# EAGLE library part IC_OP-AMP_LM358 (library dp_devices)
Dual op-amp
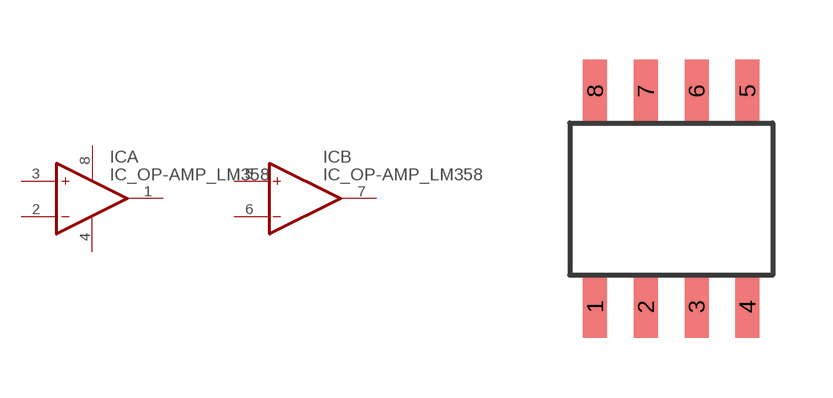
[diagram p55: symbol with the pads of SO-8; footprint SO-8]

Designator prefix IC; gates A=OPAMP_V+- B=OPAMP

## IC_OP-AMP_LM358-SO8  [SO-8]
1  A:OUT  out
2  A:-  in
3  A:+  in
4  A:V-  sup
5  B:+  in
6  B:-  in
7  B:OUT  out
8  A:V+  sup

## Footprint SO-8 (pad centres in mm)
smd 0.6 x 1.55: 1 -1.905,-2.69; 2 -0.635,-2.69; 3 0.635,-2.69; 4 1.905,-2.69; 5 1.905,2.71; 6 0.635,2.71; 7 -0.635,2.71; 8 -1.905,2.71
